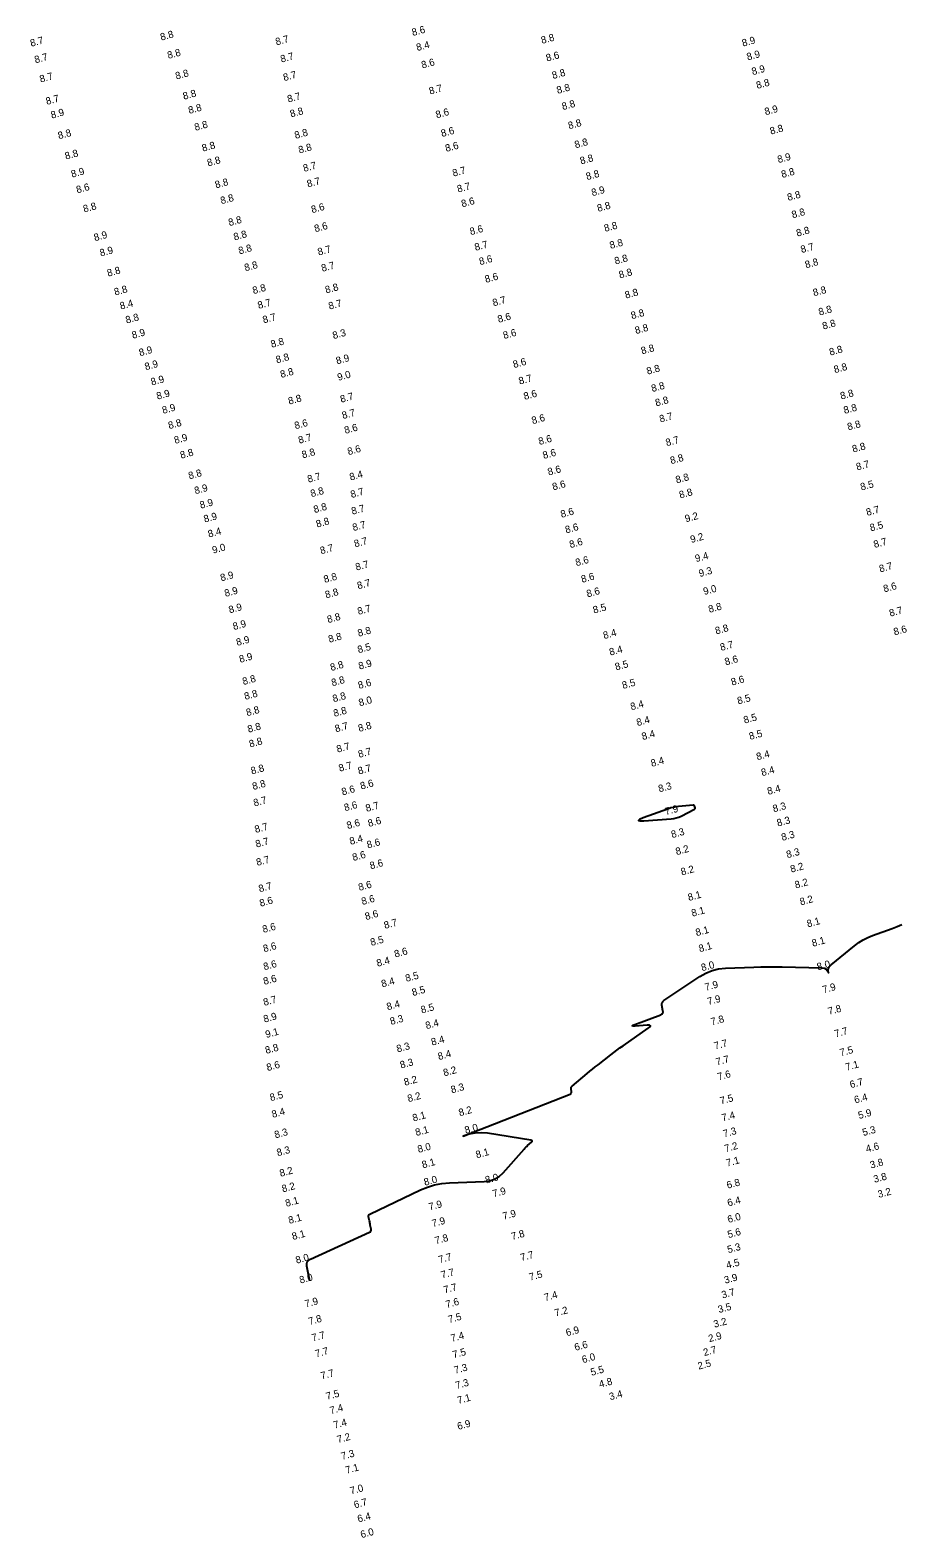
# Model space of a CAD drawing. Extents: x 988130 to 1132882, y 654656 to 841453.
# Drawn here: x 1105764 to 1106064, y 696729 to 697250 of the extents above; entities that cross this region are included whole.
import ezdxf

# ---------------------------------------------------------------- set-up
doc = ezdxf.new("R2010")
doc.units = 0
doc.layers.add('V-TOPO-MAJR', color=7, linetype='Continuous')
doc.layers.add('V-TOPO-SOUN', color=7, linetype='Continuous')

msp = doc.modelspace()

# ---------------------------------------------------------------- linework, layer by layer
at = {"layer": 'V-TOPO-MAJR'}
msp.add_lwpolyline([(1105993.88, 696982.11), (1105993.75, 696982.16), (1105993.6, 696982.16), (1105988.51, 696981.65), (1105987.62, 696981.54), (1105986.73, 696981.36), (1105985.86, 696981.14), (1105985, 696980.86), (1105976.31, 696977.73), (1105975.02, 696977.2), (1105974.62, 696976.85), (1105975.12, 696976.7), (1105976.51, 696976.73), (1105985.97, 696977.39), (1105986.87, 696977.49), (1105987.76, 696977.69), (1105988.61, 696977.98), (1105989.45, 696978.36), (1105994.06, 696980.75), (1105994.18, 696980.83), (1105994.26, 696980.94), (1105994.28, 696981.07), (1105994.25, 696981.23), (1105994.04, 696981.87), (1105993.97, 696982.01)], close=True, dxfattribs=at)
msp.add_lwpolyline([(1105860.86, 696817.4), (1105859.87, 696822.57), (1105859.83, 696823.37), (1105860.02, 696824.04), (1105860.46, 696824.59), (1105861.14, 696825.02), (1105881.57, 696834.35), (1105881.86, 696834.53), (1105882.04, 696834.76), (1105882.12, 696835.04), (1105882.1, 696835.38), (1105881.83, 696836.84), (1105881.76, 696837.19), (1105881.69, 696837.54), (1105881.62, 696837.89), (1105881.54, 696838.24), (1105881.23, 696839.63), (1105881.21, 696839.96), (1105881.28, 696840.23), (1105881.45, 696840.46), (1105881.72, 696840.64), (1105899.16, 696848.97), (1105901.59, 696849.98), (1105904.08, 696850.73), (1105906.63, 696851.22), (1105909.25, 696851.45), (1105921.22, 696851.86), (1105923.11, 696852.11), (1105924.83, 696852.7), (1105926.39, 696853.65), (1105927.78, 696854.95), (1105935.05, 696863.12), (1105935.34, 696863.45), (1105935.65, 696863.76), (1105935.97, 696864.06), (1105936.3, 696864.35), (1105937.63, 696865.5), (1105937.87, 696865.76), (1105937.91, 696865.96), (1105937.76, 696866.11), (1105937.43, 696866.21), (1105922.42, 696868.57), (1105920.26, 696868.76), (1105918.14, 696868.67), (1105916.05, 696868.28), (1105913.99, 696867.6), (1105916.03, 696868.42), (1105918.07, 696869.24), (1105920.12, 696870.05), (1105922.17, 696870.85), (1105950.99, 696882.12), (1105951.21, 696882.24), (1105951.36, 696882.41), (1105951.44, 696882.62), (1105951.44, 696882.87), (1105951.32, 696883.98), (1105951.32, 696884.24), (1105951.38, 696884.48), (1105951.5, 696884.7), (1105951.68, 696884.89), (1105956.87, 696889.24), (1105957.81, 696890.02), (1105958.75, 696890.79), (1105959.71, 696891.55), (1105960.67, 696892.3), (1105965.05, 696895.71), (1105966.11, 696896.52), (1105967.18, 696897.31), (1105968.26, 696898.1), (1105969.34, 696898.87), (1105978.06, 696904.94), (1105978.68, 696905.45), (1105978.82, 696905.79), (1105978.49, 696905.97), (1105977.69, 696905.98), (1105973.56, 696905.69), (1105972.77, 696905.67), (1105972.49, 696905.76), (1105972.71, 696905.96), (1105973.43, 696906.27), (1105982.36, 696909.6), (1105982.76, 696909.82), (1105983.02, 696910.11), (1105983.15, 696910.49), (1105983.13, 696910.94), (1105982.78, 696912.92), (1105982.76, 696913.39), (1105982.86, 696913.81), (1105983.09, 696914.17), (1105983.44, 696914.47), (1105995.85, 696922.78), (1105997.93, 696923.98), (1106000.12, 696924.87), (1106002.41, 696925.44), (1106004.8, 696925.7), (1106014.57, 696926.09), (1106017.02, 696926.17), (1106019.46, 696926.21), (1106021.91, 696926.2), (1106024.35, 696926.16), (1106038.22, 696925.81), (1106039.02, 696925.69), (1106039.65, 696925.35), (1106040.11, 696924.8), (1106040.4, 696924.05), (1106040.31, 696924.87), (1106040.44, 696925.62), (1106040.79, 696926.29), (1106041.36, 696926.89), (1106049.44, 696933.48), (1106050.89, 696934.56), (1106052.41, 696935.51), (1106054, 696936.32), (1106055.67, 696937.01), (1106062.5, 696939.49), (1106064.2, 696940.12), (1106065.88, 696940.8)], dxfattribs=at)

# ---------------------------------------------------------------- texts
at = {"layer": 'V-TOPO-SOUN'}
for s, p in [('8.8', (1105809.47, 697246.65)), ('8.6', (1105896.54, 697248.26)), ('8.7', (1105764.45, 697244.54)), ('8.7', (1105849.35, 697245.01)), ('8.4', (1105898.11, 697243.05)), ('8.8', (1105941.27, 697245.55)), ('8.9', (1106010.83, 697244.58)), ('8.7', (1105765.93, 697238.81)), ('8.8', (1105811.93, 697240.35)), ('8.7', (1105851.07, 697239.05)), ('8.6', (1105899.85, 697237)), ('8.6', (1105942.99, 697239.43)), ('8.9', (1106012.47, 697239.81)), ('8.7', (1105767.71, 697232.13)), ('8.8', (1105814.69, 697233.2)), ('8.7', (1105852.02, 697232.65)), ('8.8', (1105945.09, 697233.37)), ('8.9', (1106014.19, 697234.72)), ('8.8', (1105817.3, 697226.21)), ('8.7', (1105902.51, 697227.98)), ('8.8', (1105946.68, 697228.25)), ('8.8', (1106015.77, 697229.95)), ('8.7', (1105769.86, 697224.43)), ('8.8', (1105819.18, 697221.3)), ('8.7', (1105853.46, 697225.22)), ('8.8', (1105948.47, 697222.63)), ('8.9', (1106018.66, 697220.84)), ('8.9', (1105771.58, 697219.66)), ('8.8', (1105821.29, 697215.46)), ('8.8', (1105854.38, 697220.09)), ('8.6', (1105904.81, 697219.78)), ('8.8', (1105950.65, 697216)), ('8.8', (1105774.04, 697212.54)), ('8.8', (1105855.95, 697212.66)), ('8.6', (1105906.64, 697213.31)), ('8.8', (1106020.51, 697214.13)), ('8.8', (1105776.45, 697205.49)), ('8.8', (1105823.88, 697208.24)), ('8.8', (1105857.29, 697207.58)), ('8.6', (1105908.12, 697208.16)), ('8.8', (1105952.88, 697209.4)), ('8.8', (1105825.7, 697203.13)), ('8.7', (1105858.92, 697201.25)), ('8.7', (1105910.61, 697199.59)), ('8.8', (1105954.76, 697203.82)), ('8.9', (1106023.11, 697204.29)), ('8.9', (1105778.59, 697199.24)), ('8.8', (1105828.41, 697195.53)), ('8.7', (1105860.24, 697195.85)), ('8.8', (1105956.84, 697198.39)), ('8.8', (1106024.44, 697199.13)), ('8.6', (1105780.38, 697193.82)), ('8.8', (1105830.3, 697190.05)), ('8.7', (1105912.22, 697194.08)), ('8.9', (1105958.73, 697192.83)), ('8.8', (1106026.51, 697191.19)), ('8.8', (1105782.77, 697187.18)), ('8.6', (1105861.72, 697186.95)), ('8.6', (1105913.67, 697188.98)), ('8.8', (1105960.71, 697187.41)), ('8.8', (1106028.04, 697185.18)), ('8.8', (1105833.05, 697182.48)), ('8.6', (1105862.8, 697180.37)), ('8.6', (1105916.6, 697179.35)), ('8.8', (1105963.09, 697180.5)), ('8.8', (1106029.63, 697178.83)), ('8.9', (1105786.5, 697177.26)), ('8.8', (1105834.84, 697177.5)), ('8.7', (1105918.27, 697173.92)), ('8.8', (1105965.02, 697174.59)), ('8.9', (1105788.53, 697171.94)), ('8.8', (1105836.54, 697172.7)), ('8.7', (1105863.95, 697172.3)), ('8.6', (1105919.83, 697168.97)), ('8.8', (1105966.7, 697169.17)), ('8.7', (1106031.15, 697173.15)), ('8.8', (1105791.06, 697164.98)), ('8.8', (1105838.59, 697166.85)), ('8.7', (1105865.22, 697166.67)), ('8.8', (1105968.22, 697164.35)), ('8.8', (1106032.65, 697167.88)), ('8.8', (1105793.5, 697158.44)), ('8.8', (1105841.41, 697158.95)), ('8.8', (1105866.53, 697159.17)), ('8.6', (1105921.84, 697162.84)), ('8.8', (1106035.4, 697158.2)), ('8.4', (1105795.48, 697153.59)), ('8.7', (1105843.19, 697153.82)), ('8.7', (1105867.7, 697153.58)), ('8.7', (1105924.49, 697154.72)), ('8.8', (1105970.3, 697157.38)), ('8.8', (1105797.46, 697148.75)), ('8.7', (1105844.92, 697148.81)), ('8.6', (1105926.25, 697149.02)), ('8.8', (1105972.4, 697150.27)), ('8.8', (1106037.34, 697151.52)), ('8.9', (1105799.62, 697143.5)), ('8.3', (1105869.11, 697143.38)), ('8.6', (1105928.14, 697143.41)), ('8.8', (1105973.79, 697145.12)), ('8.8', (1106038.66, 697146.66)), ('8.9', (1105802.1, 697137.45)), ('8.8', (1105847.7, 697140.38)), ('8.8', (1105975.88, 697138.08)), ('8.8', (1106041.05, 697137.65)), ('8.9', (1105804.08, 697132.6)), ('8.8', (1105849.47, 697134.99)), ('8.9', (1105870.29, 697134.64)), ('8.6', (1105931.56, 697133.35)), ('8.9', (1105806.21, 697127.31)), ('8.8', (1105851.01, 697129.93)), ('9.0', (1105870.77, 697128.94)), ('8.7', (1105933.54, 697127.63)), ('8.8', (1105977.82, 697131.06)), ('8.8', (1106042.64, 697131.59)), ('8.9', (1105808.16, 697122.42)), ('8.7', (1105871.76, 697121.36)), ('8.6', (1105935.26, 697122.34)), ('8.8', (1105979.46, 697125.05)), ('8.8', (1106044.86, 697122.46)), ('8.9', (1105810.11, 697117.52)), ('8.8', (1105853.75, 697120.7)), ('8.8', (1105980.8, 697120.09)), ('8.8', (1106046.01, 697117.5)), ('8.8', (1105812.22, 697112.23)), ('8.6', (1105855.92, 697112.19)), ('8.7', (1105872.37, 697115.71)), ('8.6', (1105938.03, 697113.95)), ('8.7', (1105982.25, 697114.5)), ('8.8', (1106047.3, 697111.78)), ('8.9', (1105814.27, 697107.14)), ('8.7', (1105857.26, 697107.17)), ('8.6', (1105873.19, 697110.6)), ('8.6', (1105940.39, 697106.73)), ('8.7', (1105984.43, 697106.32)), ('8.8', (1105816.34, 697101.98)), ('8.8', (1105858.46, 697102.11)), ('8.6', (1105874.28, 697103.23)), ('8.6', (1105941.86, 697101.9)), ('8.8', (1106048.99, 697104.1)), ('8.6', (1105943.57, 697096.18)), ('8.8', (1105985.99, 697100.1)), ('8.7', (1106050.34, 697097.91)), ('8.8', (1105819.21, 697094.85)), ('8.7', (1105860.41, 697093.68)), ('8.4', (1105874.99, 697094.43)), ('8.6', (1105945.17, 697091.02)), ('8.8', (1105987.87, 697093.43)), ('8.5', (1106051.82, 697090.98)), ('8.9', (1105821.28, 697089.7)), ('8.8', (1105861.48, 697088.67)), ('8.7', (1105875.33, 697088.39)), ('8.8', (1105989.09, 697088.22)), ('8.9', (1105823.14, 697084.69)), ('8.9', (1105824.51, 697079.88)), ('8.8', (1105862.54, 697083.18)), ('8.7', (1105875.63, 697082.6)), ('8.6', (1105948.04, 697081.54)), ('9.2', (1105991.08, 697079.99)), ('8.7', (1106053.83, 697082.19)), ('8.4', (1105825.97, 697074.7)), ('8.8', (1105863.39, 697078.14)), ('8.7', (1105875.99, 697076.95)), ('8.6', (1105949.63, 697076.16)), ('8.5', (1106055.09, 697076.84)), ('8.7', (1105876.57, 697071.32)), ('8.6', (1105951.09, 697071.06)), ('9.2', (1105992.95, 697072.82)), ('8.7', (1106056.39, 697071.1)), ('9.0', (1105827.44, 697069.14)), ('8.7', (1105864.8, 697068.93)), ('8.6', (1105953.18, 697064.8)), ('9.4', (1105994.6, 697066.21)), ('8.9', (1105830.26, 697059.55)), ('8.8', (1105866.04, 697059.01)), ('8.7', (1105877.03, 697063.26)), ('8.6', (1105955.14, 697059.06)), ('9.3', (1105995.88, 697061.05)), ('8.7', (1106058.32, 697062.66)), ('8.9', (1105831.7, 697054.17)), ('8.8', (1105866.54, 697053.67)), ('8.7', (1105877.63, 697056.81)), ('8.6', (1105957.02, 697054.01)), ('9.0', (1105997.43, 697054.83)), ('8.6', (1106059.78, 697055.74)), ('8.9', (1105833.15, 697048.46)), ('8.5', (1105959.25, 697048.39)), ('8.8', (1105999.2, 697048.67)), ('8.8', (1105867.24, 697045.11)), ('8.7', (1105877.74, 697047.95)), ('8.7', (1106061.82, 697047.32)), ('8.9', (1105834.57, 697042.69)), ('8.8', (1105867.66, 697038.3)), ('8.8', (1105877.8, 697040.38)), ('8.4', (1105962.78, 697039.58)), ('8.8', (1106001.55, 697041.2)), ('8.6', (1106063.31, 697040.83)), ('8.9', (1105835.76, 697037.2)), ('8.5', (1105877.76, 697034.68)), ('8.4', (1105964.9, 697033.84)), ('8.7', (1106003.27, 697035.48)), ('8.9', (1105836.79, 697031.36)), ('8.8', (1105868.31, 697028.52)), ('8.9', (1105878.08, 697029)), ('8.5', (1105966.88, 697028.72)), ('8.6', (1106004.85, 697030.46)), ('8.8', (1105837.91, 697023.67)), ('8.8', (1105868.71, 697023.25)), ('8.6', (1105877.93, 697022.32)), ('8.5', (1105969.34, 697022.32)), ('8.6', (1106007.05, 697023.46)), ('8.8', (1105838.55, 697018.52)), ('8.8', (1105869.11, 697017.72)), ('8.5', (1106009.2, 697016.96)), ('8.8', (1105839.19, 697012.89)), ('8.8', (1105869.41, 697012.65)), ('8.0', (1105878.15, 697016.31)), ('8.4', (1105972.22, 697014.94)), ('8.8', (1105839.69, 697007.17)), ('8.7', (1105869.91, 697007.31)), ('8.8', (1105877.98, 697007.46)), ('8.4', (1105974.32, 697009.46)), ('8.5', (1106011.38, 697010.32)), ('8.8', (1105840.21, 697002.04)), ('8.4', (1105976.12, 697004.62)), ('8.5', (1106013.29, 697004.69)), ('8.7', (1105870.49, 697000.27)), ('8.7', (1105877.96, 696998.5)), ('8.4', (1106015.81, 696997.64)), ('8.8', (1105840.82, 696992.72)), ('8.7', (1105871.23, 696993.67)), ('8.7', (1105877.88, 696992.7)), ('8.4', (1105979.27, 696995.36)), ('8.4', (1106017.48, 696992.14)), ('8.8', (1105841.33, 696987.35)), ('8.6', (1105878.69, 696987.5)), ('8.3', (1105981.89, 696986.55)), ('8.7', (1105841.72, 696981.64)), ('8.6', (1105872.23, 696985.48)), ('8.4', (1106019.6, 696985.67)), ('8.6', (1105873.1, 696980)), ('8.7', (1105880.56, 696979.79)), ('7.9', (1105984.15, 696978.66)), ('8.3', (1106021.48, 696979.63)), ('8.7', (1105842.14, 696972.48)), ('8.6', (1105874, 696973.82)), ('8.6', (1105881.34, 696974.56)), ('8.3', (1105986.3, 696970.71)), ('8.3', (1106022.91, 696974.7)), ('8.7', (1105842.43, 696967.41)), ('8.4', (1105875.01, 696968.37)), ('8.6', (1105880.98, 696967.11)), ('8.3', (1106024.46, 696969.75)), ('8.7', (1105842.71, 696961.07)), ('8.6', (1105875.97, 696962.78)), ('8.6', (1105881.99, 696959.9)), ('8.2', (1105987.86, 696964.81)), ('8.3', (1106026.19, 696963.76)), ('8.2', (1105989.67, 696957.77)), ('8.2', (1106027.58, 696958.74)), ('8.7', (1105843.51, 696951.96)), ('8.6', (1105878.04, 696952.46)), ('8.2', (1106029.1, 696953.25)), ('8.6', (1105843.84, 696946.95)), ('8.6', (1105879.1, 696947.55)), ('8.1', (1105992.1, 696948.94)), ('8.2', (1106030.85, 696947.41)), ('8.6', (1105880.33, 696942.33)), ('8.7', (1105886.91, 696939.3)), ('8.1', (1105993.33, 696943.5)), ('8.1', (1106033.27, 696939.81)), ('8.6', (1105844.84, 696937.89)), ('8.1', (1105994.78, 696936.78)), ('8.6', (1105845.08, 696931.2)), ('8.5', (1105882.2, 696933.39)), ('8.6', (1105890.47, 696929.36)), ('8.1', (1105995.86, 696931.23)), ('8.1', (1106035.01, 696933.11)), ('8.6', (1105845.17, 696924.98)), ('8.4', (1105884.34, 696926.18)), ('8.0', (1105996.69, 696924.64)), ('8.0', (1106036.77, 696924.91)), ('8.6', (1105845.14, 696919.92)), ('8.4', (1105885.98, 696919.03)), ('8.5', (1105894.31, 696920.96)), ('7.9', (1105997.97, 696917.87)), ('8.7', (1105845.14, 696912.66)), ('8.5', (1105896.58, 696916.05)), ('7.9', (1105998.84, 696912.92)), ('7.9', (1106038.68, 696917.02)), ('8.4', (1105887.82, 696911.12)), ('8.5', (1105899.66, 696910.01)), ('7.8', (1106040.61, 696909.52)), ('8.9', (1105845.19, 696906.85)), ('8.3', (1105889.01, 696906.04)), ('8.4', (1105901.28, 696904.58)), ('7.8', (1106000.03, 696905.91)), ('9.1', (1105845.85, 696901.54)), ('8.4', (1105903.23, 696898.89)), ('7.7', (1106001.19, 696897.54)), ('7.7', (1106042.84, 696901.76)), ('8.8', (1105845.8, 696896.03)), ('8.3', (1105891.25, 696896.55)), ('8.4', (1105905.55, 696893.89)), ('7.7', (1106001.81, 696892.01)), ('7.5', (1106044.7, 696895.22)), ('8.6', (1105846.26, 696890.09)), ('8.3', (1105892.46, 696890.96)), ('8.2', (1105907.43, 696888.26)), ('7.6', (1106002.33, 696886.87)), ('7.1', (1106046.64, 696890.22)), ('8.2', (1105893.82, 696885)), ('8.3', (1105910.05, 696882.39)), ('6.7', (1106048.17, 696884.15)), ('8.5', (1105847.39, 696879.68)), ('8.2', (1105895.05, 696879.34)), ('7.5', (1106003.21, 696878.54)), ('6.4', (1106049.68, 696878.88)), ('8.4', (1105848.04, 696873.9)), ('8.1', (1105896.78, 696872.61)), ('8.2', (1105912.77, 696874.46)), ('7.4', (1106003.82, 696872.65)), ('5.9', (1106051.06, 696873.5)), ('8.3', (1105848.99, 696866.8)), ('8.1', (1105897.77, 696867.62)), ('8.0', (1105914.85, 696868.39)), ('7.3', (1106004.3, 696867.16)), ('5.3', (1106052.51, 696867.6)), ('8.3', (1105849.78, 696860.62)), ('8.0', (1105898.53, 696861.78)), ('7.2', (1106004.76, 696862.03)), ('4.6', (1106053.69, 696861.91)), ('8.1', (1105900.03, 696856.43)), ('8.1', (1105918.67, 696859.91)), ('7.1', (1106005.35, 696857.03)), ('3.8', (1106055.16, 696856.34)), ('8.2', (1105850.78, 696853.5)), ('8.0', (1105900.73, 696850.4)), ('8.0', (1105921.94, 696851.14)), ('3.8', (1106056.35, 696851.42)), ('8.2', (1105851.54, 696848.11)), ('7.9', (1105924.49, 696846.41)), ('6.8', (1106005.54, 696849.37)), ('3.2', (1106057.85, 696846.2)), ('8.1', (1105852.77, 696843.12)), ('7.9', (1105902.4, 696841.87)), ('6.4', (1106005.77, 696843.23)), ('8.1', (1105853.82, 696837.2)), ('7.9', (1105903.49, 696836.1)), ('7.9', (1105928, 696838.63)), ('6.0', (1106005.82, 696837.52)), ('8.1', (1105855.05, 696831.62)), ('7.8', (1105904.53, 696830.18)), ('7.8', (1105930.96, 696831.62)), ('5.6', (1106005.83, 696832.27)), ('7.7', (1105934.12, 696824.33)), ('5.3', (1106005.76, 696827.07)), ('8.0', (1105856.32, 696823.43)), ('7.7', (1105905.75, 696823.59)), ('4.5', (1106005.37, 696821.66)), ('8.0', (1105857.64, 696816.54)), ('7.7', (1105906.66, 696818.29)), ('7.5', (1105937.16, 696817.57)), ('3.9', (1106004.67, 696816.51)), ('7.7', (1105907.55, 696813.12)), ('7.4', (1105942.36, 696810.49)), ('3.7', (1106003.76, 696811.39)), ('7.9', (1105859.5, 696808.27)), ('7.6', (1105908.28, 696808.09)), ('7.2', (1105945.96, 696805.13)), ('3.5', (1106002.54, 696806.36)), ('7.8', (1105860.75, 696802.23)), ('7.5', (1105909.12, 696802.91)), ('6.9', (1105949.86, 696798.32)), ('3.2', (1106000.98, 696801.26)), ('7.7', (1105861.91, 696796.53)), ('7.4', (1105910.04, 696796.39)), ('6.6', (1105952.83, 696793.27)), ('2.9', (1105999.2, 696796.29)), ('7.7', (1105863.08, 696791.03)), ('7.5', (1105910.67, 696790.7)), ('6.0', (1105955.43, 696789.01)), ('2.7', (1105997.43, 696791.46)), ('7.7', (1105865.01, 696783.39)), ('7.3', (1105911.19, 696785.35)), ('5.5', (1105958.43, 696784.64)), ('2.5', (1105995.52, 696786.77)), ('7.3', (1105911.64, 696780.08)), ('4.8', (1105961.33, 696780.49)), ('7.5', (1105866.84, 696776.3)), ('7.1', (1105912.28, 696774.89)), ('3.4', (1105964.87, 696776.18)), ('7.4', (1105868.15, 696771.38)), ('7.4', (1105869.43, 696766.36)), ('7.2', (1105870.65, 696761.35)), ('6.9', (1105912.27, 696765.93)), ('7.3', (1105872.07, 696755.57)), ('7.1', (1105873.58, 696750.75)), ('7.0', (1105875.15, 696743.58)), ('6.7', (1105876.49, 696738.75)), ('6.4', (1105877.73, 696733.88)), ('6.0', (1105878.78, 696728.47))]:
    msp.add_text(s, height=2.5, rotation=15, dxfattribs=at).set_placement(p)

doc.saveas('drawing.dxf')
